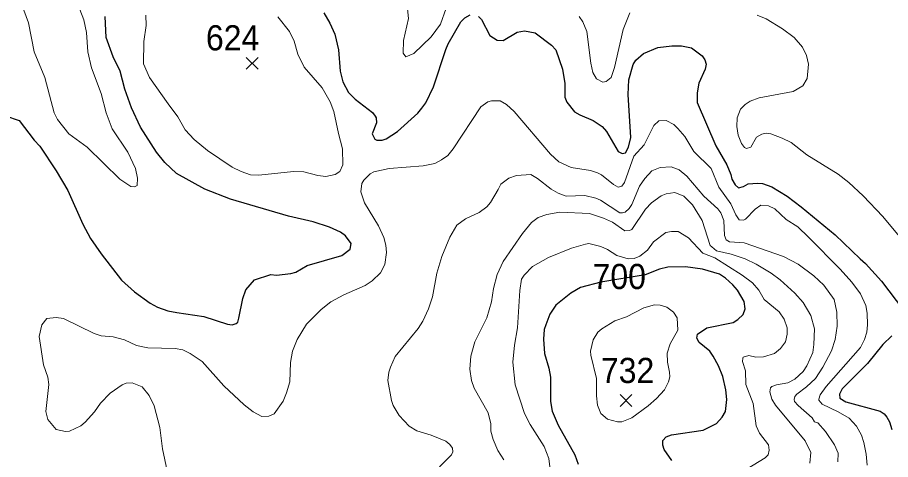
# Model space of a CAD drawing. Extents: x 294.2 to 320.3, y 7482.7 to 7510.7.
# Drawn here: x 295.794 to 298.568, y 7488.966 to 7490.371 of the extents above; entities that cross this region are included whole.
import ezdxf
from ezdxf.enums import TextEntityAlignment as Align

# ---------------------------------------------------------------- set-up
doc = ezdxf.new("R2010")
doc.units = 0
doc.header["$LTSCALE"] = 0.032
for name, color, linetype, lineweight in [('1', 7, 'Continuous', 25), ('2', 7, 'Continuous', 13), ('21', 7, 'Continuous', 25)]:
    doc.layers.add(name, color=color, linetype=linetype, lineweight=lineweight)
doc.layers.add('61', color=7, linetype='Continuous')

msp = doc.modelspace()

# ---------------------------------------------------------------- linework, layer by layer
at = {"layer": '1'}
for points in [[(296.1557, 7490.0846), (296.1353, 7490.1433), (296.12, 7490.2008), (296.0983, 7490.2468), (296.0753, 7490.3081), (296.0723, 7490.3746)], [(296.7667, 7490.386), (296.7859, 7490.3528), (296.8019, 7490.3183), (296.814, 7490.2685), (296.8191, 7490.2008), (296.8274, 7490.1664), (296.8459, 7490.1331), (296.867, 7490.1114), (296.9219, 7490.0693), (296.9302, 7490.0578), (296.9334, 7490.0521), (296.934, 7490.0367), (296.9212, 7490.0016), (296.9289, 7489.985), (296.9353, 7489.9812), (296.9525, 7489.9812), (296.9653, 7489.9856), (297.0017, 7490.0086), (297.0662, 7490.0674), (297.0789, 7490.0834), (297.091, 7490.1), (297.116, 7490.151), (297.1543, 7490.2698), (297.1626, 7490.2877), (297.2022, 7490.3572), (297.2156, 7490.3707), (297.2322, 7490.3796)], [(297.2584, 7490.3745), (297.2679, 7490.3649), (297.2947, 7490.3145), (297.3177, 7490.2991), (297.3369, 7490.2985), (297.3816, 7490.3247), (297.4046, 7490.3285), (297.4384, 7490.3228), (297.4907, 7490.2838), (297.5042, 7490.2685), (297.5259, 7490.2072), (297.5329, 7490.1612), (297.5329, 7490.1178), (297.5393, 7490.1025), (297.5636, 7490.0719), (297.5802, 7490.0616), (297.6229, 7490.0438), (297.6517, 7490.0246), (297.6657, 7490.0093), (297.7027, 7489.9454), (297.7155, 7489.939), (297.7257, 7489.9416), (297.7353, 7489.9595), (297.7423, 7489.9901), (297.7346, 7490.1268), (297.7366, 7490.1727), (297.75, 7490.2219)], [(297.75, 7490.2219), (297.7589, 7490.2359), (297.7826, 7490.257), (297.8285, 7490.2755), (297.8732, 7490.2813), (297.9039, 7490.2813), (297.9358, 7490.2749)], [(297.9358, 7490.2749), (297.969, 7490.2493), (297.9779, 7490.2372), (297.9824, 7490.2225), (297.9792, 7490.2072), (297.9588, 7490.1625), (297.953, 7490.1319), (297.9537, 7490.1012), (298.013, 7489.9633), (298.0482, 7489.9033), (298.0609, 7489.8727), (298.0641, 7489.8573), (298.0737, 7489.8394), (298.0852, 7489.8298), (298.1005, 7489.8337), (298.1158, 7489.8426), (298.1452, 7489.8452), (298.1605, 7489.8433), (298.1912, 7489.8331), (298.2397, 7489.8037), (298.2844, 7489.7698), (298.3923, 7489.6804), (298.4709, 7489.6047), (298.4887, 7489.5891), (298.5391, 7489.5336), (298.6087, 7489.441)], [(296.4711, 7489.7941), (296.3894, 7489.826), (296.2994, 7489.8758), (296.2617, 7489.9109), (296.2355, 7489.9435), (296.1844, 7490.0233), (296.1557, 7490.0846)], [(295.756, 7490.0591), (295.7988, 7490.0444), (295.8467, 7489.9812), (295.8646, 7489.9626), (295.9169, 7489.8841), (295.954, 7489.8216), (296.0012, 7489.7143), (296.0255, 7489.6689), (296.0593, 7489.6198), (296.1247, 7489.5365), (296.1658, 7489.4999), (296.2157, 7489.4634), (296.2387, 7489.4506), (296.2719, 7489.4391), (296.3, 7489.434), (296.3855, 7489.4206), (296.4609, 7489.3963), (296.4762, 7489.3944), (296.489, 7489.3989), (296.4935, 7489.4027), (296.4973, 7489.4155), (296.5094, 7489.4781), (296.5196, 7489.5062), (296.5465, 7489.5374), (296.5988, 7489.5547), (296.6167, 7489.5527), (296.6627, 7489.5572), (296.678, 7489.5623), (296.7138, 7489.5834), (296.8248, 7489.6147), (296.851, 7489.6351), (296.8536, 7489.653), (296.8363, 7489.6773), (296.8197, 7489.6888), (296.7853, 7489.7047), (296.7329, 7489.722), (296.655, 7489.7398), (296.4711, 7489.7941)], [(297.8725, 7488.9635), (297.849, 7488.9979), (297.8439, 7489.012), (297.8445, 7489.0273), (297.8553, 7489.0382), (297.872, 7489.0452), (297.9728, 7489.0598), (298.015, 7489.0815), (298.0328, 7489.1007), (298.0431, 7489.1192), (298.0475, 7489.1576), (298.0449, 7489.1882), (298.0347, 7489.2303), (298.0213, 7489.2648), (298.0041, 7489.2955), (297.9932, 7489.3108), (297.9601, 7489.3389), (297.9528, 7489.3518), (297.955, 7489.3647), (297.9839, 7489.3846), (298.0679, 7489.4021), (298.0826, 7489.4117), (298.0999, 7489.427), (298.1056, 7489.4455), (298.1031, 7489.4691), (298.0814, 7489.5049), (298.0666, 7489.5221), (298.0437, 7489.5426), (298.0239, 7489.5553), (297.9703, 7489.5713), (297.9166, 7489.5789), (297.8605, 7489.5777), (297.8336, 7489.5713), (297.7877, 7489.554), (297.6471, 7489.53), (297.5827, 7489.5135), (297.5521, 7489.4947), (297.5048, 7489.4576), (297.485, 7489.4282), (297.4723, 7489.3951), (297.4678, 7489.3798), (297.4652, 7489.3491), (297.4684, 7489.3031), (297.4825, 7489.2572), (297.4876, 7489.2278), (297.4869, 7489.1512), (297.4927, 7489.1205), (297.5118, 7489.0758), (297.5648, 7488.9813), (297.5757, 7488.952)], [(298.5723, 7489.36), (298.5436, 7489.3319), (298.4942, 7489.2715), (298.4146, 7489.1908), (298.4057, 7489.1747), (298.4063, 7489.1613), (298.4257, 7489.1494), (298.5353, 7489.1199), (298.5481, 7489.1115), (298.5557, 7489.1014), (298.5647, 7489.0867), (298.5723, 7489.0624)]]:
    msp.add_lwpolyline(points, dxfattribs=at)
at = {"layer": '2'}
for points in [[(295.8135, 7490.3949), (295.8288, 7490.3541), (295.8467, 7490.2621), (295.8811, 7490.1804), (295.9099, 7490.068), (295.9207, 7490.0476), (295.9565, 7490.0016), (296.0152, 7489.9588), (296.1186, 7489.8573), (296.1544, 7489.8343), (296.1659, 7489.833), (296.1736, 7489.8369), (296.1748, 7489.8612), (296.1684, 7489.8918), (296.1442, 7489.9429), (296.0944, 7490.017), (296.0752, 7490.068), (296.0599, 7490.1293), (296.0293, 7490.211), (296.0172, 7490.2621), (296.0127, 7490.3234), (296.005, 7490.3643), (295.9846, 7490.4154)], [(297.0329, 7490.3988), (297.0362, 7490.3681), (297.0202, 7490.2979), (297.0189, 7490.2583), (297.0272, 7490.2468), (297.0528, 7490.2564), (297.1083, 7490.3094), (297.1383, 7490.3502), (297.1562, 7490.4013)], [(296.6205, 7490.3732), (296.6582, 7490.3273), (296.6728, 7490.2966), (296.6843, 7490.2545), (296.7048, 7490.2136), (296.7616, 7490.1478), (296.7872, 7490.1038), (296.7987, 7490.0731), (296.8133, 7490.0029), (296.8267, 7489.9544), (296.8274, 7489.9033), (296.8178, 7489.8822), (296.8037, 7489.872), (296.7738, 7489.8662), (296.7482, 7489.8688), (296.7035, 7489.8803), (296.6703, 7489.8822), (296.5605, 7489.8701), (296.5337, 7489.8713), (296.5043, 7489.8815), (296.4762, 7489.8956), (296.3971, 7489.9486), (296.3549, 7489.9831), (296.3262, 7490.0144), (296.3032, 7490.0553), (296.2726, 7490.0974), (296.2131, 7490.1804), (296.194, 7490.2244), (296.1953, 7490.2953), (296.2029, 7490.3464), (296.2011, 7490.3783)], [(297.5782, 7490.3745), (297.5904, 7490.3579), (297.6025, 7490.3273), (297.6152, 7490.2264), (297.6223, 7490.197), (297.6331, 7490.1765), (297.6536, 7490.1663), (297.6638, 7490.1676), (297.6798, 7490.1804), (297.6906, 7490.2123), (297.7181, 7490.3336), (297.7391, 7490.386)], [(298.1439, 7490.379), (298.1727, 7490.3668), (298.2244, 7490.3355), (298.2614, 7490.3074), (298.2876, 7490.2774), (298.301, 7490.2506), (298.3067, 7490.2225), (298.3029, 7490.1778), (298.2895, 7490.1542), (298.2589, 7490.1363), (298.1503, 7490.1159), (298.1222, 7490.1057), (298.1062, 7490.0948), (298.0909, 7490.0795), (298.08, 7490.0527), (298.0794, 7490.0246), (298.0839, 7489.9978), (298.0948, 7489.971), (298.1037, 7489.9582), (298.1107, 7489.955), (298.1235, 7489.9595), (298.142, 7489.9908), (298.1593, 7490.0003), (298.1726, 7490.0035), (298.1874, 7490.0016), (298.2231, 7489.9882), (298.2518, 7489.9742), (298.3023, 7489.9352), (298.4012, 7489.8733), (298.435, 7489.8471), (298.481, 7489.805), (298.543, 7489.7392), (298.6215, 7489.6441)], [(298.4932, 7488.9481), (298.49, 7488.9839), (298.483, 7489.0209), (298.4753, 7489.0439), (298.4593, 7489.072), (298.4364, 7489.0975), (298.4019, 7489.1186), (298.3508, 7489.1428), (298.3399, 7489.155), (298.3399, 7489.1588), (298.3438, 7489.1716), (298.3629, 7489.199), (298.4721, 7489.3223), (298.4849, 7489.3478), (298.4925, 7489.3708), (298.4951, 7489.3951), (298.4938, 7489.4321), (298.4894, 7489.4564), (298.4727, 7489.4934), (298.4447, 7489.5304), (298.4082, 7489.5712), (298.3073, 7489.6728), (298.2729, 7489.706), (298.2358, 7489.7296), (298.2001, 7489.7635), (298.1803, 7489.773), (298.1554, 7489.775), (298.1375, 7489.7622), (298.1069, 7489.7309), (298.1011, 7489.727), (298.0871, 7489.7283), (298.0762, 7489.7437), (298.0603, 7489.7794), (298.0226, 7489.8318), (297.9983, 7489.8912), (297.9428, 7489.9454), (297.9147, 7489.9927), (297.8917, 7490.0189), (297.8796, 7490.031), (297.8554, 7490.0444), (297.8311, 7490.0425), (297.8157, 7490.0284), (297.7851, 7489.9671), (297.7525, 7489.9301), (297.7225, 7489.8471), (297.7136, 7489.8356), (297.7021, 7489.8324), (297.6874, 7489.8407), (297.6498, 7489.8713), (297.637, 7489.8777), (297.614, 7489.8848), (297.5527, 7489.8943), (297.5138, 7489.9129), (297.4875, 7489.9365), (297.372, 7490.0725), (297.3471, 7490.0948), (297.3279, 7490.107), (297.2999, 7490.107), (297.2884, 7490.1038), (297.266, 7490.0872), (297.1785, 7489.9544), (297.1607, 7489.9326), (297.1415, 7489.9186), (297.1198, 7489.9078), (297.0828, 7489.8994), (296.9743, 7489.8918), (296.9257, 7489.8803), (296.9149, 7489.8746), (296.8938, 7489.8548), (296.8881, 7489.8433), (296.8848, 7489.8177), (296.8963, 7489.782), (296.9404, 7489.7092), (296.9583, 7489.6722), (296.9647, 7489.6479), (296.9665, 7489.6249), (296.9608, 7489.5866), (296.9468, 7489.5598), (296.9206, 7489.5342), (296.8989, 7489.5196), (296.8306, 7489.4895), (296.7897, 7489.4672), (296.7584, 7489.4436)], [(298.2621, 7489.1576), (298.2639, 7489.1665), (298.2697, 7489.1741), (298.301, 7489.1971), (298.3291, 7489.2239), (298.3527, 7489.2597), (298.3801, 7489.3121), (298.3916, 7489.3478), (298.398, 7489.39), (298.3974, 7489.4347), (298.3891, 7489.4755), (298.3559, 7489.5202), (298.324, 7489.5508), (298.2748, 7489.5878), (298.2282, 7489.6115), (298.1031, 7489.6555), (298.0558, 7489.6581), (298.0456, 7489.6645), (298.0405, 7489.6786), (298.0386, 7489.7258), (298.0284, 7489.7501), (298.0194, 7489.7628), (297.9747, 7489.803), (297.9211, 7489.8675), (297.8962, 7489.8873), (297.8707, 7489.8969), (297.8362, 7489.895), (297.8093, 7489.8835), (297.787, 7489.8599), (297.7704, 7489.8356), (297.7455, 7489.7769), (297.7372, 7489.7641), (297.7251, 7489.7526), (297.7162, 7489.7507), (297.7078, 7489.7507), (297.6466, 7489.7909), (297.6319, 7489.7973), (297.5961, 7489.8056), (297.5374, 7489.8037), (297.5119, 7489.8126), (297.4895, 7489.8254), (297.446, 7489.8598), (297.425, 7489.872), (297.379, 7489.8688), (297.3548, 7489.8605), (297.3298, 7489.8414), (297.3209, 7489.8247)], [(297.3209, 7489.8247), (297.2967, 7489.7833), (297.2852, 7489.7698), (297.2603, 7489.752), (297.2175, 7489.7315), (297.19, 7489.7111), (297.1677, 7489.6735), (297.1422, 7489.6122), (297.1262, 7489.5585), (297.1121, 7489.4832), (297.0993, 7489.4449), (297.0821, 7489.4066), (297.0674, 7489.3829), (296.994, 7489.2935), (296.9787, 7489.2597), (296.9736, 7489.2444), (296.9704, 7489.2175), (296.9825, 7489.1537), (296.9877, 7489.1384), (297.0068, 7489.1065), (297.0387, 7489.072), (297.0624, 7489.0579), (297.1083, 7489.0439), (297.1543, 7489.0247), (297.1677, 7489.0139), (297.176, 7489.0024), (297.1772, 7488.9909), (297.1728, 7488.9813), (297.1351, 7488.943)], [(298.2901, 7489.4653), (298.2639, 7489.4947), (298.2173, 7489.5374), (298.1886, 7489.5585), (298.1414, 7489.5878), (298.1056, 7489.6044), (298.0615, 7489.6192), (298.015, 7489.63), (297.9996, 7489.6422), (297.9952, 7489.6466), (297.969, 7489.7258), (297.939, 7489.7756), (297.9109, 7489.8037), (297.8822, 7489.8151), (297.8554, 7489.8113), (297.8388, 7489.8049), (297.8081, 7489.7826), (297.7896, 7489.7622), (297.7455, 7489.6977), (297.7385, 7489.6945), (297.7238, 7489.6938), (297.6842, 7489.7207), (297.6555, 7489.7341), (297.6115, 7489.7481), (297.517, 7489.7526), (297.4761, 7489.7449)], [(297.4761, 7489.7449), (297.448, 7489.7354), (297.4269, 7489.7194), (297.3982, 7489.6849), (297.3369, 7489.5956), (297.3177, 7489.5547), (297.3062, 7489.51), (297.2998, 7489.4679), (297.2852, 7489.4168), (297.2475, 7489.3402), (297.2347, 7489.2955), (297.2309, 7489.2533), (297.236, 7489.2176), (297.2449, 7489.1933), (297.2896, 7489.1154), (297.2973, 7489.0797), (297.2979, 7489.0567), (297.3049, 7489.0299), (297.3203, 7488.9954), (297.3388, 7488.966)], [(298.0099, 7489.6077), (297.9709, 7489.6223), (297.9262, 7489.6709), (297.893, 7489.6907), (297.872, 7489.6913), (297.8534, 7489.6875), (297.8151, 7489.6588), (297.7956, 7489.6319)], [(297.7956, 7489.6319), (297.7711, 7489.6128), (297.7532, 7489.6057), (297.734, 7489.6044), (297.6983, 7489.6147), (297.6682, 7489.6345), (297.6478, 7489.644), (297.6089, 7489.653), (297.5987, 7489.6511), (297.554, 7489.6383), (297.4812, 7489.6089), (297.4307, 7489.5802), (297.4033, 7489.5527), (297.3956, 7489.54), (297.3899, 7489.5036), (297.3822, 7489.3849), (297.3726, 7489.33), (297.3675, 7489.2763), (297.3752, 7489.2035), (297.4046, 7489.1129), (297.4231, 7489.0777), (297.4678, 7489.0082), (297.4824, 7488.9698), (297.485, 7488.943)], [(298.2295, 7489.413), (298.2135, 7489.4359), (298.1663, 7489.4755), (298.149, 7489.5049), (298.1292, 7489.5285), (298.0967, 7489.5528), (298.0099, 7489.6077)], [(298.2901, 7489.2463), (298.3022, 7489.2648), (298.3214, 7489.307), (298.3239, 7489.3325), (298.3259, 7489.3823), (298.315, 7489.4244), (298.2901, 7489.4653)], [(296.7584, 7489.4436), (296.7118, 7489.3964), (296.6825, 7489.3478), (296.6677, 7489.3108), (296.6614, 7489.275), (296.6588, 7489.2137), (296.6486, 7489.178)], [(296.6486, 7489.178), (296.6384, 7489.1525), (296.609, 7489.1115), (296.5924, 7489.1046), (296.5701, 7489.1033), (296.5426, 7489.1186), (296.5139, 7489.1403), (296.4494, 7489.201), (296.3805, 7489.2776), (296.3422, 7489.3038), (296.3192, 7489.3153), (296.2949, 7489.3191), (296.2081, 7489.3216), (296.1723, 7489.3286), (296.134, 7489.3472), (296.0983, 7489.3561), (296.06, 7489.36), (296.037, 7489.3669), (295.9399, 7489.4142), (295.9169, 7489.418), (295.8875, 7489.4142), (295.8716, 7489.3951), (295.8627, 7489.358), (295.8767, 7489.2674), (295.8901, 7489.2278), (295.8933, 7489.2048), (295.8837, 7489.1193), (295.8907, 7489.0937), (295.9163, 7489.0624), (295.9463, 7489.056), (295.9591, 7489.0567), (295.9948, 7489.0739), (296.0088, 7489.0848), (296.0389, 7489.1186), (296.058, 7489.146), (296.088, 7489.1773), (296.1263, 7489.2035), (296.1391, 7489.2092), (296.1582, 7489.2105), (296.1895, 7489.1978), (296.2125, 7489.1703), (296.2279, 7489.1371), (296.2457, 7489.0682), (296.2547, 7489.0005), (296.277, 7488.8958)], [(298.0877, 7488.9226), (298.1695, 7488.9724), (298.1791, 7488.9819), (298.1822, 7488.9967), (298.1803, 7489.0132), (298.1516, 7489.0503), (298.1413, 7489.0733), (298.1318, 7489.1448), (298.1081, 7489.2048), (298.1069, 7489.2488), (298.0979, 7489.2776), (298.0986, 7489.2891), (298.0992, 7489.2923), (298.1171, 7489.2967), (298.1401, 7489.2923), (298.1644, 7489.2929), (298.1989, 7489.3038), (298.218, 7489.3191), (298.234, 7489.3402), (298.2397, 7489.3644), (298.2397, 7489.3855), (298.2295, 7489.413)], [(298.3112, 7488.9551), (298.315, 7488.989), (298.2965, 7489.026), (298.202, 7489.139), (298.1911, 7489.1588), (298.1842, 7489.1818), (298.186, 7489.1939), (298.1912, 7489.1984), (298.2052, 7489.2042), (298.241, 7489.2099), (298.264, 7489.222), (298.2901, 7489.2463)], [(298.361, 7489.056), (298.3367, 7489.0828), (298.3265, 7489.0866), (298.3188, 7489.0988), (298.2748, 7489.1378), (298.2627, 7489.1512), (298.2621, 7489.1576)], [(298.4006, 7488.9596), (298.4012, 7488.9865), (298.3903, 7489.0133), (298.361, 7489.056)]]:
    msp.add_lwpolyline(points, dxfattribs=at)
msp.add_lwpolyline([(297.8183, 7489.4582), (297.7838, 7489.4487), (297.7289, 7489.42), (297.6919, 7489.4072), (297.6504, 7489.3823), (297.6383, 7489.3708), (297.6229, 7489.3466), (297.6146, 7489.3108), (297.6152, 7489.298), (297.6331, 7489.224), (297.6331, 7489.1691), (297.6369, 7489.1397), (297.6478, 7489.1129), (297.6689, 7489.095), (297.7008, 7489.086), (297.7136, 7489.086), (297.7455, 7489.0995), (297.7979, 7489.1371), (297.8247, 7489.1601), (297.8496, 7489.1882), (297.8624, 7489.2137), (297.8662, 7489.2291), (297.8655, 7489.2444), (297.8591, 7489.2763), (297.8579, 7489.3044), (297.8681, 7489.3338), (297.8917, 7489.3778), (297.8898, 7489.4168), (297.8783, 7489.4353), (297.8566, 7489.4512), (297.8362, 7489.4576)], close=True, dxfattribs=at)
at = {"layer": '21'}
for p, q in [((296.5205, 7490.2442), (296.558, 7490.2067)), ((296.558, 7490.2442), (296.5205, 7490.2067)), ((297.7084, 7489.1727), (297.7459, 7489.1352)), ((297.7459, 7489.1727), (297.7084, 7489.1352))]:
    msp.add_line(p, q, dxfattribs=at)

# ---------------------------------------------------------------- texts
at = {"layer": '61', "width": 0.95}
for s, p in [('624', (296.4773, 7490.2668)), ('700', (297.7059, 7489.5082)), ('732', (297.7324, 7489.2096))]:
    msp.add_text(s, height=0.08, dxfattribs=at).set_placement(p, align=Align.CENTER)

doc.saveas('drawing.dxf')
